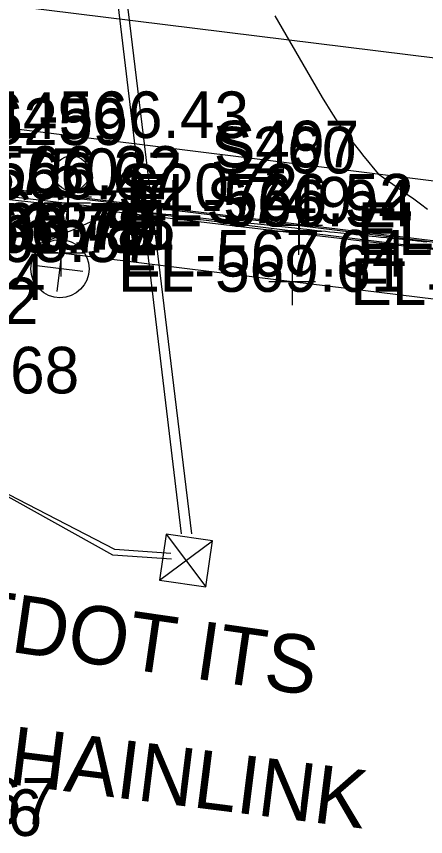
# Model space of a CAD drawing. Extents: x 1724534 to 1727318, y 657156 to 660047.
# Drawn here: x 1725557.2 to 1725592.4, y 658521 to 658591.4 of the extents above; entities that cross this region are included whole.
import ezdxf

# ---------------------------------------------------------------- set-up
doc = ezdxf.new("R2010")
doc.units = 0
for name, color, linetype in [('SURVEY - CONTOURS - Intermediate with optional Text', 7, 'Continuous'), ('SURVEY - DRAINAGE - Area Shapes', 7, 'Continuous'), ('SURVEY - DTM - Breaklines', 7, 'Continuous'), ('SURVEY - DTM - Breaklines - Points - Elevations', 7, 'Continuous'), ('SURVEY - DTM - Breaklines - Points - Locators', 7, 'Continuous'), ('SURVEY - DTM - Breaklines - Points - Numbers', 7, 'Continuous'), ('SURVEY - NON-TRANSPORTATION - Features - Points - Elevations', 7, 'Continuous'), ('SURVEY - NON-TRANSPORTATION - Features Text', 7, 'Continuous'), ('SURVEY - ROADSIDE BARRIERS - Points - Elevations', 7, 'Continuous'), ('SURVEY - ROADSIDE BARRIERS - Points - Locators', 7, 'Continuous'), ('SURVEY - ROADSIDE BARRIERS - Points - Numbers', 7, 'Continuous'), ('SURVEY - ROADSIDE BARRIERS with Text', 7, 'Continuous'), ('SURVEY - TRAFFIC CONTROL - Pavement Marking with Text', 7, 'Continuous'), ('SURVEY - TRAFFIC CONTROL - Signs - Points - Elevations', 7, 'Continuous'), ('SURVEY - TRANSPORTATION - Features', 7, 'Continuous'), ('SURVEY - TRANSPORTATION - Features - Points - Elevations', 7, 'Continuous'), ('SURVEY - TRANSPORTATION - Features - Points - Locators', 7, 'Continuous'), ('SURVEY - TRANSPORTATION - Features - Points - Numbers', 7, 'Continuous'), ('SURVEY - TRANSPORTATION - Roads', 7, 'Continuous'), ('SURVEY - TRANSPORTATION - Roads - Points - Elevations', 7, 'Continuous'), ('SURVEY - UTILITIES - Electric (Lighting) - Points - Elevations', 7, 'Continuous'), ('SURVEY - UTILITIES - Electric (Lighting) - Points - Locators', 7, 'Continuous'), ('SURVEY - UTILITIES - Electric (Lighting) - Points - Numbers', 7, 'Continuous'), ('SURVEY - UTILITIES - Electric (Lighting) with Text', 7, 'Continuous'), ('SURVEY - UTILITIES - Electric (Underground) with Text', 7, 'Continuous'), ('SURVEY - UTILITIES - Fiber Optic Cable (Underground) with Text', 7, 'Continuous'), ('SURVEY - UTILITIES - Poles and Miscellaneous - Points - Elevations', 7, 'Continuous'), ('SURVEY - UTILITIES - Poles and Miscellaneous with Text', 7, 'Continuous'), ('SURVEY - VEGETATION - Features - Points - Elevations', 7, 'Continuous')]:
    doc.layers.add(name, color=color, linetype=linetype)

msp = doc.modelspace()

# ---------------------------------------------------------------- linework, layer by layer
at = {"layer": 'SURVEY - CONTOURS - Intermediate with optional Text'}
for points in [[(1725579.394, 658591.488), (1725582.428, 658586.255), (1725583.476, 658584.472), (1725584.346, 658583.05), (1725585.036, 658581.987), (1725585.548, 658581.284), (1725586.676, 658579.89), (1725587.059, 658579.415), (1725587.366, 658579.036), (1725587.595, 658578.753), (1725587.747, 658578.565), (1725588.273, 658577.914), (1725590.792, 658576.149), (1725591.343, 658575.756), (1725591.916, 658575.334), (1725592.512, 658574.882)], [(1725592.462, 658572.044), (1725592.153, 658572.076), (1725591.97, 658572.095), (1725591.651, 658572.129), (1725591.482, 658572.147), (1725591.213, 658572.175), (1725590.846, 658572.213), (1725590.379, 658572.262), (1725589.002, 658572.405), (1725588.522, 658572.455), (1725588.113, 658572.498), (1725587.776, 658572.533), (1725587.51, 658572.561), (1725586.898, 658572.626), (1725586.646, 658572.653), (1725586.349, 658572.684), (1725586.007, 658572.72), (1725585.621, 658572.76), (1725584.53, 658572.874), (1725584.13, 658572.916), (1725583.748, 658572.956), (1725583.384, 658572.995), (1725583.038, 658573.031), (1725582.14, 658573.127), (1725581.845, 658573.158), (1725581.634, 658573.181), (1725581.508, 658573.194), (1725581.465, 658573.199), (1725581.465, 658573.199), (1725581.465, 658573.199), (1725581.465, 658573.199), (1725581.465, 658573.199), (1725581.465, 658573.199), (1725581.464, 658573.199), (1725581.425, 658573.203), (1725581.307, 658573.216), (1725581.11, 658573.238), (1725580.834, 658573.268), (1725579.993, 658573.359), (1725579.664, 658573.395), (1725579.305, 658573.434), (1725578.918, 658573.475), (1725578.502, 658573.52), (1725577.354, 658573.642), (1725576.949, 658573.685), (1725576.598, 658573.723), (1725576.299, 658573.755), (1725576.053, 658573.782), (1725575.468, 658573.845), (1725575.21, 658573.873), (1725574.875, 658573.909), (1725574.464, 658573.953), (1725573.976, 658574.005), (1725572.573, 658574.154), (1725572.097, 658574.205), (1725571.723, 658574.244), (1725571.451, 658574.274), (1725571.28, 658574.292), (1725570.959, 658574.327), (1725570.776, 658574.346), (1725570.466, 658574.379), (1725570.03, 658574.426), (1725569.467, 658574.485), (1725567.799, 658574.662), (1725567.249, 658574.721), (1725566.852, 658574.763), (1725566.607, 658574.789), (1725566.514, 658574.799), (1725566.469, 658574.803), (1725566.441, 658574.806), (1725566.392, 658574.812), (1725566.322, 658574.819), (1725566.23, 658574.829), (1725565.752, 658574.879), (1725563.964, 658573.983), (1725563.592, 658573.798), (1725563.243, 658573.631), (1725562.917, 658573.479), (1725562.614, 658573.344), (1725561.834, 658573.004), (1725561.579, 658572.893), (1725561.396, 658572.813), (1725561.286, 658572.766), (1725561.25, 658572.75), (1725561.25, 658572.749), (1725561.249, 658572.749), (1725561.249, 658572.749), (1725561.249, 658572.749), (1725561.249, 658572.749), (1725561.249, 658572.749), (1725561.226, 658572.739), (1725561.158, 658572.707), (1725561.045, 658572.655), (1725560.886, 658572.582), (1725560.404, 658572.36), (1725560.204, 658572.274), (1725559.967, 658572.181), (1725559.693, 658572.081), (1725559.382, 658571.975), (1725557.843, 658571.465)]]:
    msp.add_lwpolyline(points, dxfattribs=at)
at = {"layer": 'SURVEY - DRAINAGE - Area Shapes'}
msp.add_lwpolyline([(1725876.527, 658537.521), (1725880.453, 658568.253), (1725462.782, 658619.36), (1725459.014, 658588.567)], close=True, dxfattribs=at)
at = {"layer": 'SURVEY - DTM - Breaklines'}
msp.add_lwpolyline([(1725489.875, 658584.035), (1725509.601, 658581.531), (1725526.033, 658579.596), (1725541.721, 658577.725), (1725561.584, 658575.392), (1725581.434, 658572.95), (1725601.283, 658570.508), (1725621.131, 658568.058), (1725640.981, 658565.625), (1725660.832, 658563.199), (1725680.682, 658560.757), (1725700.532, 658558.327)], dxfattribs=at)
at = {"layer": 'SURVEY - DTM - Breaklines - Points - Locators'}
for p, q in [((1725561.584, 658577.392), (1725561.584, 658573.392)), ((1725563.584, 658575.392), (1725559.584, 658575.392)), ((1725581.434, 658574.95), (1725581.434, 658570.95)), ((1725583.434, 658572.95), (1725579.434, 658572.95))]:
    msp.add_line(p, q, dxfattribs=at)
at = {"layer": 'SURVEY - ROADSIDE BARRIERS - Points - Locators'}
for p, q in [((1725561.039, 658573.092), (1725561.039, 658569.092)), ((1725563.039, 658571.092), (1725559.039, 658571.092)), ((1725580.889, 658570.65), (1725580.889, 658566.65)), ((1725582.889, 658568.65), (1725578.889, 658568.65))]:
    msp.add_line(p, q, dxfattribs=at)
at = {"layer": 'SURVEY - ROADSIDE BARRIERS with Text'}
msp.add_lwpolyline([(1725762.719, 658545.483), (1725760.676, 658546.181), (1725739.67, 658549.027), (1725719.83, 658551.532), (1725699.981, 658553.973), (1725680.133, 658556.429), (1725660.282, 658558.858), (1725640.433, 658561.304), (1725620.586, 658563.762), (1725600.739, 658566.219), (1725580.889, 658568.65), (1725561.039, 658571.092), (1725541.174, 658573.41), (1725539.632, 658573.409), (1725538.14, 658573.134)], dxfattribs=at)
at = {"layer": 'SURVEY - TRAFFIC CONTROL - Pavement Marking with Text'}
msp.add_lwpolyline([(1725507.893, 658598.435), (1725611.44, 658585.624), (1725663.045, 658579.239), (1725732.511, 658570.646), (1725771.433, 658565.831), (1725828.993, 658558.789), (1725876.604, 658552.91), (1725911.384, 658548.615)], dxfattribs=at)
at = {"layer": 'SURVEY - TRANSPORTATION - Features'}
msp.add_lwpolyline([(1725489.947, 658584.602), (1725509.681, 658582.097), (1725524.934, 658580.3), (1725526.112, 658580.162), (1725541.793, 658578.292), (1725561.649, 658575.907), (1725581.5, 658573.471), (1725601.349, 658571.032), (1725621.199, 658568.593), (1725641.048, 658566.157), (1725660.9, 658563.739), (1725680.75, 658561.297), (1725700.601, 658558.867)], dxfattribs=at)
at = {"layer": 'SURVEY - TRANSPORTATION - Features - Points - Locators'}
for p, q in [((1725561.649, 658577.907), (1725561.649, 658573.907)), ((1725563.649, 658575.907), (1725559.649, 658575.907)), ((1725581.5, 658575.471), (1725581.5, 658571.471)), ((1725583.5, 658573.471), (1725579.5, 658573.471))]:
    msp.add_line(p, q, dxfattribs=at)
at = {"layer": 'SURVEY - TRANSPORTATION - Roads'}
msp.add_lwpolyline([(1725460.854, 658593.916), (1725508.47, 658587.877), (1725514.425, 658587.132), (1725525.683, 658585.724), (1725547.511, 658582.986), (1725616.971, 658574.343), (1725730.092, 658560.27)], dxfattribs=at)
at = {"layer": 'SURVEY - UTILITIES - Electric (Lighting) - Points - Locators'}
for p, q in [((1725561.182, 658571.766), (1725560.696, 658567.796)), ((1725562.924, 658569.538), (1725558.954, 658570.024))]:
    msp.add_line(p, q, dxfattribs=at)
at = {"layer": 'SURVEY - UTILITIES - Electric (Lighting) with Text'}
msp.add_line((1725561.77, 658576.47), (1725561.254, 658572.251), dxfattribs=at)
for centre, radius in [((1725561.952, 658577.958), 1.5), ((1725560.95, 658569.769), 2.5)]:
    msp.add_circle(centre, radius, dxfattribs=at)
at = {"layer": 'SURVEY - UTILITIES - Electric (Underground) with Text'}
for points in [[(1725557.505, 658671.143), (1725558.426, 658655.231), (1725571.365, 658546.997)], [(1725505.901, 658581.192), (1725559.522, 658575.408), (1725608.231, 658569.636), (1725663.449, 658562.739), (1725716.937, 658556.185), (1725775.83, 658548.079)], [(1725570.465, 658545.323), (1725565.665, 658545.645), (1725533.361, 658562.337), (1725527.597, 658562.481)]]:
    msp.add_lwpolyline(points, dxfattribs=at)
at = {"layer": 'SURVEY - UTILITIES - Fiber Optic Cable (Underground) with Text'}
for points in [[(1725558.069, 658671.315), (1725558.963, 658656.482), (1725572.239, 658547)], [(1725570.544, 658544.832), (1725565.502, 658545.166), (1725533.562, 658562.952), (1725528.58, 658563.313), (1725528.948, 658565.808)]]:
    msp.add_lwpolyline(points, dxfattribs=at)
at = {"layer": 'SURVEY - UTILITIES - Poles and Miscellaneous with Text'}
for p, q in [((1725570.082, 658546.971), (1725573.466, 658542.439)), ((1725569.508, 658543.013), (1725574.04, 658546.397)), ((1725571.774, 658544.705), (1725571.774, 658544.705))]:
    msp.add_line(p, q, dxfattribs=at)
msp.add_lwpolyline([(1725570.082, 658546.971), (1725569.508, 658543.013), (1725573.466, 658542.439), (1725574.04, 658546.397), (1725570.082, 658546.971)], dxfattribs=at)

# ---------------------------------------------------------------- texts
at = {"layer": 'SURVEY - DTM - Breaklines - Points - Elevations'}
for s, p in [('EL-566.67', (1725546.721, 658575.725)), ('EL-566.94', (1725566.584, 658573.392)), ('EL-567.22', (1725586.434, 658570.95))]:
    msp.add_text(s, height=4, dxfattribs=at).set_placement(p)
at = {"layer": 'SURVEY - DTM - Breaklines - Points - Numbers'}
for s, p in [('S259', (1725554.232, 658580.392)), ('S260', (1725573.925, 658577.95))]:
    msp.add_text(s, height=4, dxfattribs=at).set_placement(p)
at = {"layer": 'SURVEY - NON-TRANSPORTATION - Features - Points - Elevations'}
for s, p in [('EL-565.57', (1725544.441, 658570.338)), ('EL-565.68', (1725537.926, 658559.059)), ('EL-566.67', (1725535.925, 658522.045))]:
    msp.add_text(s, height=4, dxfattribs=at).set_placement(p)
at = {"layer": 'SURVEY - NON-TRANSPORTATION - Features Text'}
msp.add_text('CHAINLINK', height=5, rotation=352.83376, dxfattribs=at).set_placement((1725551.603, 658526.133))
at = {"layer": 'SURVEY - ROADSIDE BARRIERS - Points - Elevations'}
for s, p in [('EL-566.78', (1725543.14, 658571.134)), ('EL-566.79', (1725544.632, 658571.409)), ('EL-566.81', (1725546.174, 658571.41)), ('EL-568.55', (1725546.174, 658571.404)), ('EL-567.04', (1725566.039, 658569.092)), ('EL-567.30', (1725585.889, 658566.65))]:
    msp.add_text(s, height=4, dxfattribs=at).set_placement(p)
at = {"layer": 'SURVEY - ROADSIDE BARRIERS - Points - Numbers'}
for s, p in [('S750', (1725553.53, 658576.092)), ('S749', (1725573.537, 658573.65))]:
    msp.add_text(s, height=4, dxfattribs=at).set_placement(p)
at = {"layer": 'SURVEY - TRAFFIC CONTROL - Signs - Points - Elevations'}
msp.add_text('EL-566.82', height=4, dxfattribs=at).set_placement((1725534.422, 658565.013))
at = {"layer": 'SURVEY - TRANSPORTATION - Features - Points - Elevations'}
for s, p in [('EL-566.22', (1725546.793, 658576.292)), ('EL-566.52', (1725566.649, 658573.907)), ('EL-566.74', (1725544.364, 658572.489)), ('EL-566.78', (1725544.14, 658571.134)), ('EL-566.76', (1725586.5, 658571.471))]:
    msp.add_text(s, height=4, dxfattribs=at).set_placement(p)
at = {"layer": 'SURVEY - TRANSPORTATION - Features - Points - Numbers'}
for s, p in [('S496', (1725554.203, 658580.907)), ('S497', (1725574.164, 658578.471))]:
    msp.add_text(s, height=4, dxfattribs=at).set_placement(p)
at = {"layer": 'SURVEY - TRANSPORTATION - Roads - Points - Elevations'}
msp.add_text('EL-566.43', height=4, dxfattribs=at).set_placement((1725552.511, 658580.986))
at = {"layer": 'SURVEY - UTILITIES - Electric (Lighting) - Points - Elevations'}
msp.add_text('EL-569.61', height=4, dxfattribs=at).set_placement((1725565.939, 658567.781))
at = {"layer": 'SURVEY - UTILITIES - Electric (Lighting) - Points - Numbers'}
msp.add_text('S2072', height=4, dxfattribs=at).set_placement((1725565.939, 658574.781))
at = {"layer": 'SURVEY - UTILITIES - Poles and Miscellaneous - Points - Elevations'}
msp.add_text('EL-566.74', height=4, dxfattribs=at).set_placement((1725535.026, 658567.068))
at = {"layer": 'SURVEY - UTILITIES - Poles and Miscellaneous with Text'}
msp.add_text('TDOT ITS', height=5, rotation=351.75456, dxfattribs=at).set_placement((1725552.565, 658537.463))
at = {"layer": 'SURVEY - VEGETATION - Features - Points - Elevations'}
msp.add_text('EL-567.46', height=4, dxfattribs=at).set_placement((1725534.734, 658521.061))

doc.saveas('drawing.dxf')
